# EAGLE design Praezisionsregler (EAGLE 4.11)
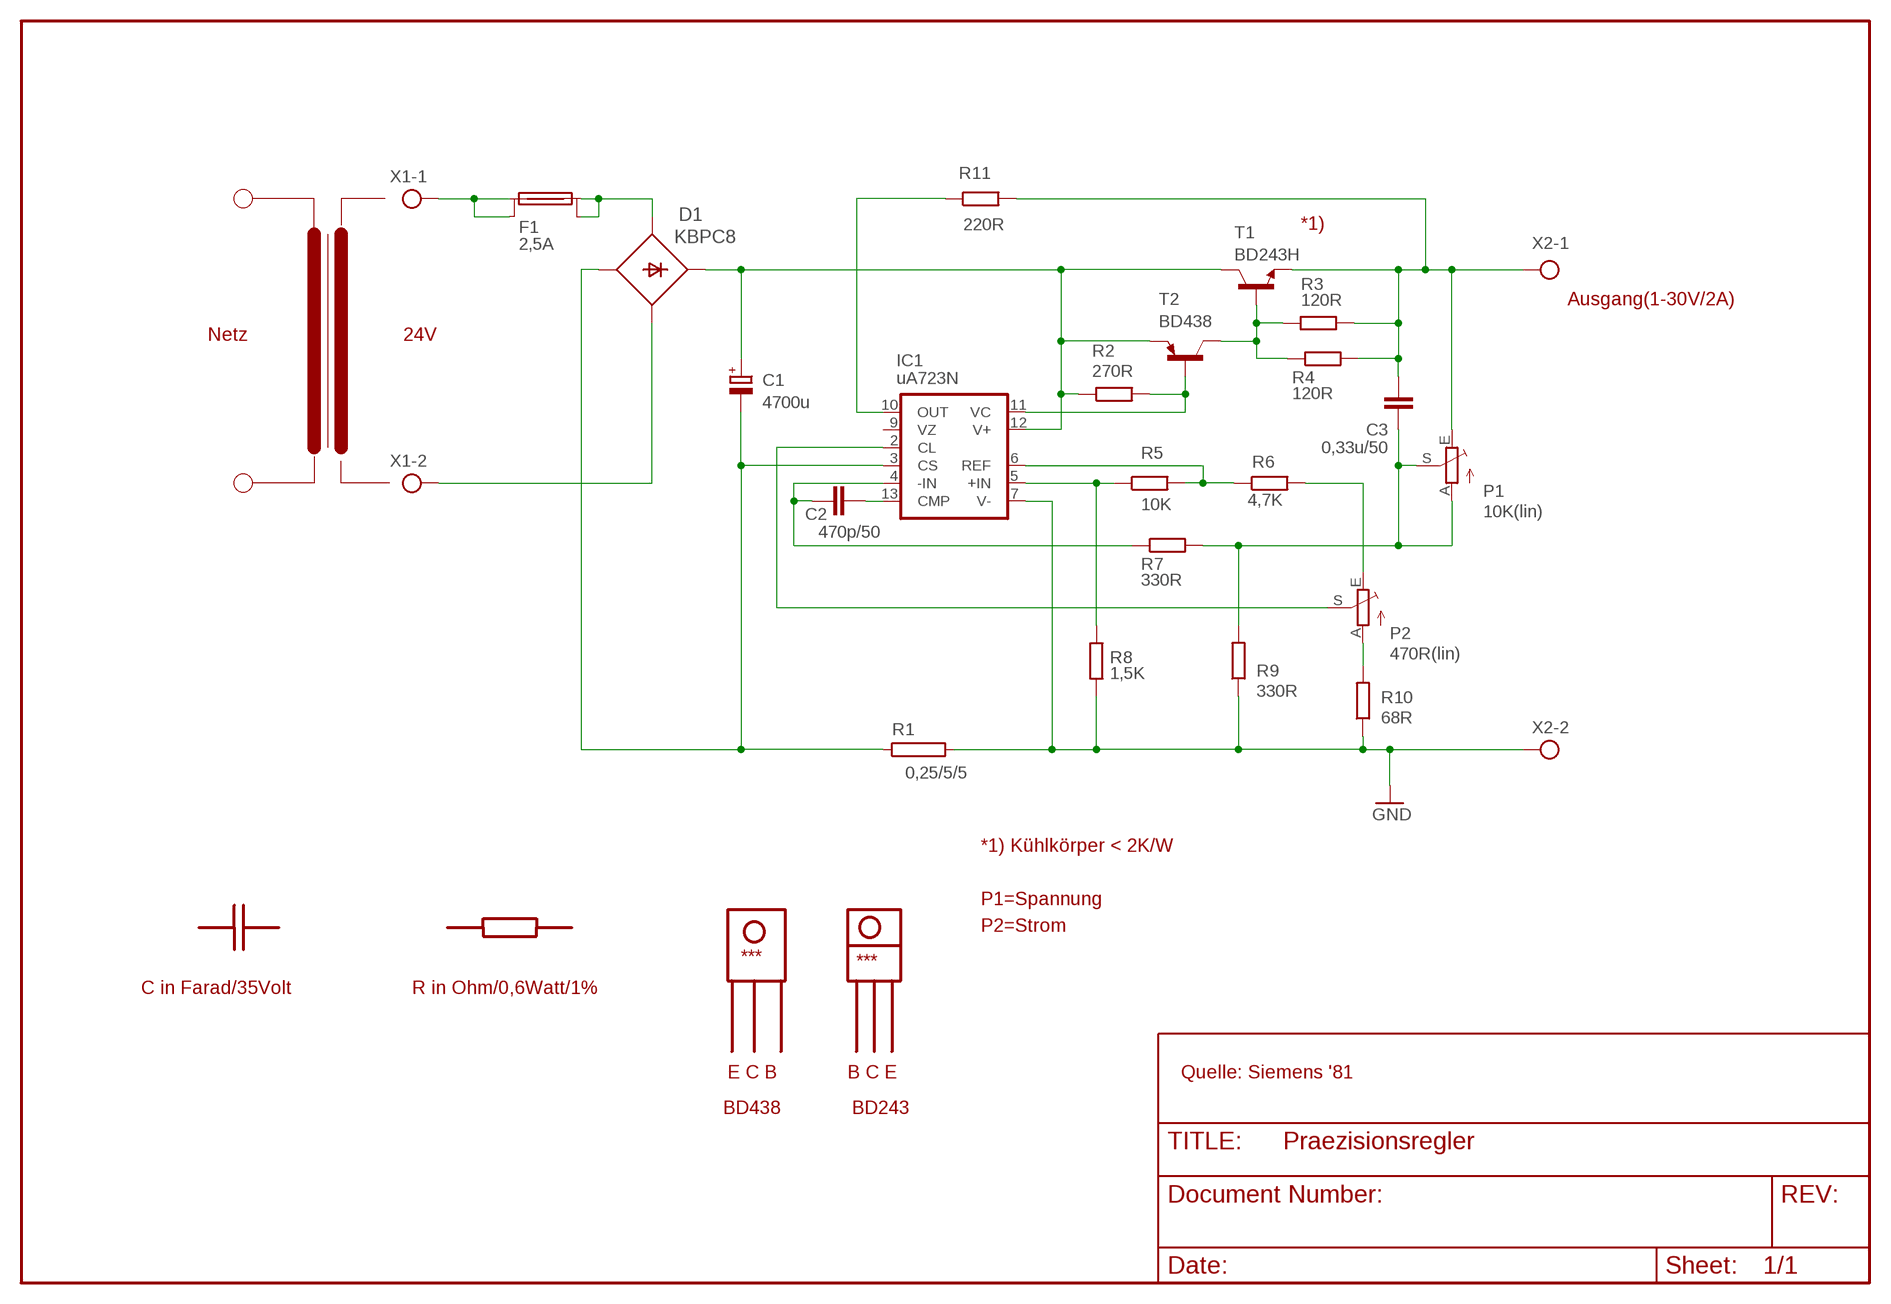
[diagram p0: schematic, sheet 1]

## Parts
C1  4700u  CPOL-EUE10-22.5  [EB22,5D]
C2  470p/50  C5/2.5  [C5B2.5]
C3  0,33u/50  C5/2.5  [C5B2.5]
D1  KBPC8  [KBPC8]
F1  2,5A  SHK20L  [SHK20L]
IC1  uA723N  [DIL14]
P1  10K(lin)  TRIM_EU-LI15  [LI15]
P2  470R(lin)  TRIM_EU-LI15  [LI15]
R1  0,25/5/5  RKH206-8  [KH206-8]
R2  270R  R-EU_0309/12  [0309/12]
R3  120R  R-EU_0309/12  [0309/12]
R4  120R  R-EU_0309/12  [0309/12]
R5  10K  R-EU_0207/10  [0207/10]
R6  4,7K  R-EU_0207/10  [0207/10]
R7  330R  R-EU_0207/10  [0207/10]
R8  1,5K  R-EU_0207/10  [0207/10]
R9  330R  R-EU_0207/10  [0207/10]
R10  68R  R-EU_0207/10  [0207/10]
R11  220R  R-EU_0207/10  [0207/10]
T1  BD243H  [TO220H]
T2  BD438  BD438V  [TO126]
X1  AK300/2  [AK300/2]
X2  AK300/2  [AK300/2]

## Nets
GND: IC1.7(V-) R1.2 R8.2 R9.1 R10.1 X2.2
N$1: F1.1A F1.1B X1.1
N$2: D1.AC2 F1.2A F1.2B
N$3: D1.AC1 X1.2
N$4: C1.+ D1.DC+ IC1.12(V+) R2.1 T1.2(C) T2.1(E)
N$5: C1.- D1.DC- IC1.3(CS) R1.1
N$6: IC1.5(+IN) R5.1 R8.1
N$7: IC1.10(OUT) R11.1
N$8: IC1.6(REF) R5.2 R6.1
N$9: IC1.2(CL) P2.S
N$10: P2.E R6.2
N$11: P2.A R10.2
N$12: C3.2 P1.A P1.S R7.2 R9.2
N$13: C2.1 IC1.4(-IN) R7.1
N$14: C3.1 P1.E R3.2 R4.2 R11.2 T1.3(E) X2.1
N$15: C2.2 IC1.13(CMP)
N$16: IC1.11(VC) R2.2 T2.3(B)
N$17: R3.1 R4.1 T1.1(B) T2.2(C)
Unconnected: IC1.9(VZ)

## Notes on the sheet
- *1)
- Ausgang(1-30V/2A)
- Netz | 24V
- *1) Kühlkörper < 2K/W
- P1=Spannung
- P2=Strom
- *** | ***
- C in Farad/35Volt | R in Ohm/0,6Watt/1%
- E C B | B C E | Quelle: Siemens '81
- BD438 | BD243

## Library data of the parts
C1 = rcl:CPOL-EU: POLARIZED CAPACITOR, European symbol
C2 C3 = capacitor-wima:C: CAPACITOR
D1 = IntergatedCircuits-mix:KBPC8: DIOTEC RECTIFIER
F1 = PassivParts:SHK20L: FUSE HOLDER 5 x 20 mm, SH contact, SHH1 Schukat, E1073 Buerklin
IC1 = linear:*723: Positive VOLTAGE REGULATOR
P1 P2 = pot:TRIM_EU-: POTENTIOMETER
R1 = resistor-power:R: Power Resitor
R2-R11 = rcl:R-EU_: RESISTOR, European symbol
T1 = transistor-mix:BD243: NPN TRANSISTOR
T2 = transistor-mix:BD438
X1 X2 = con-ptr500:AK300/2: CONNECTOR

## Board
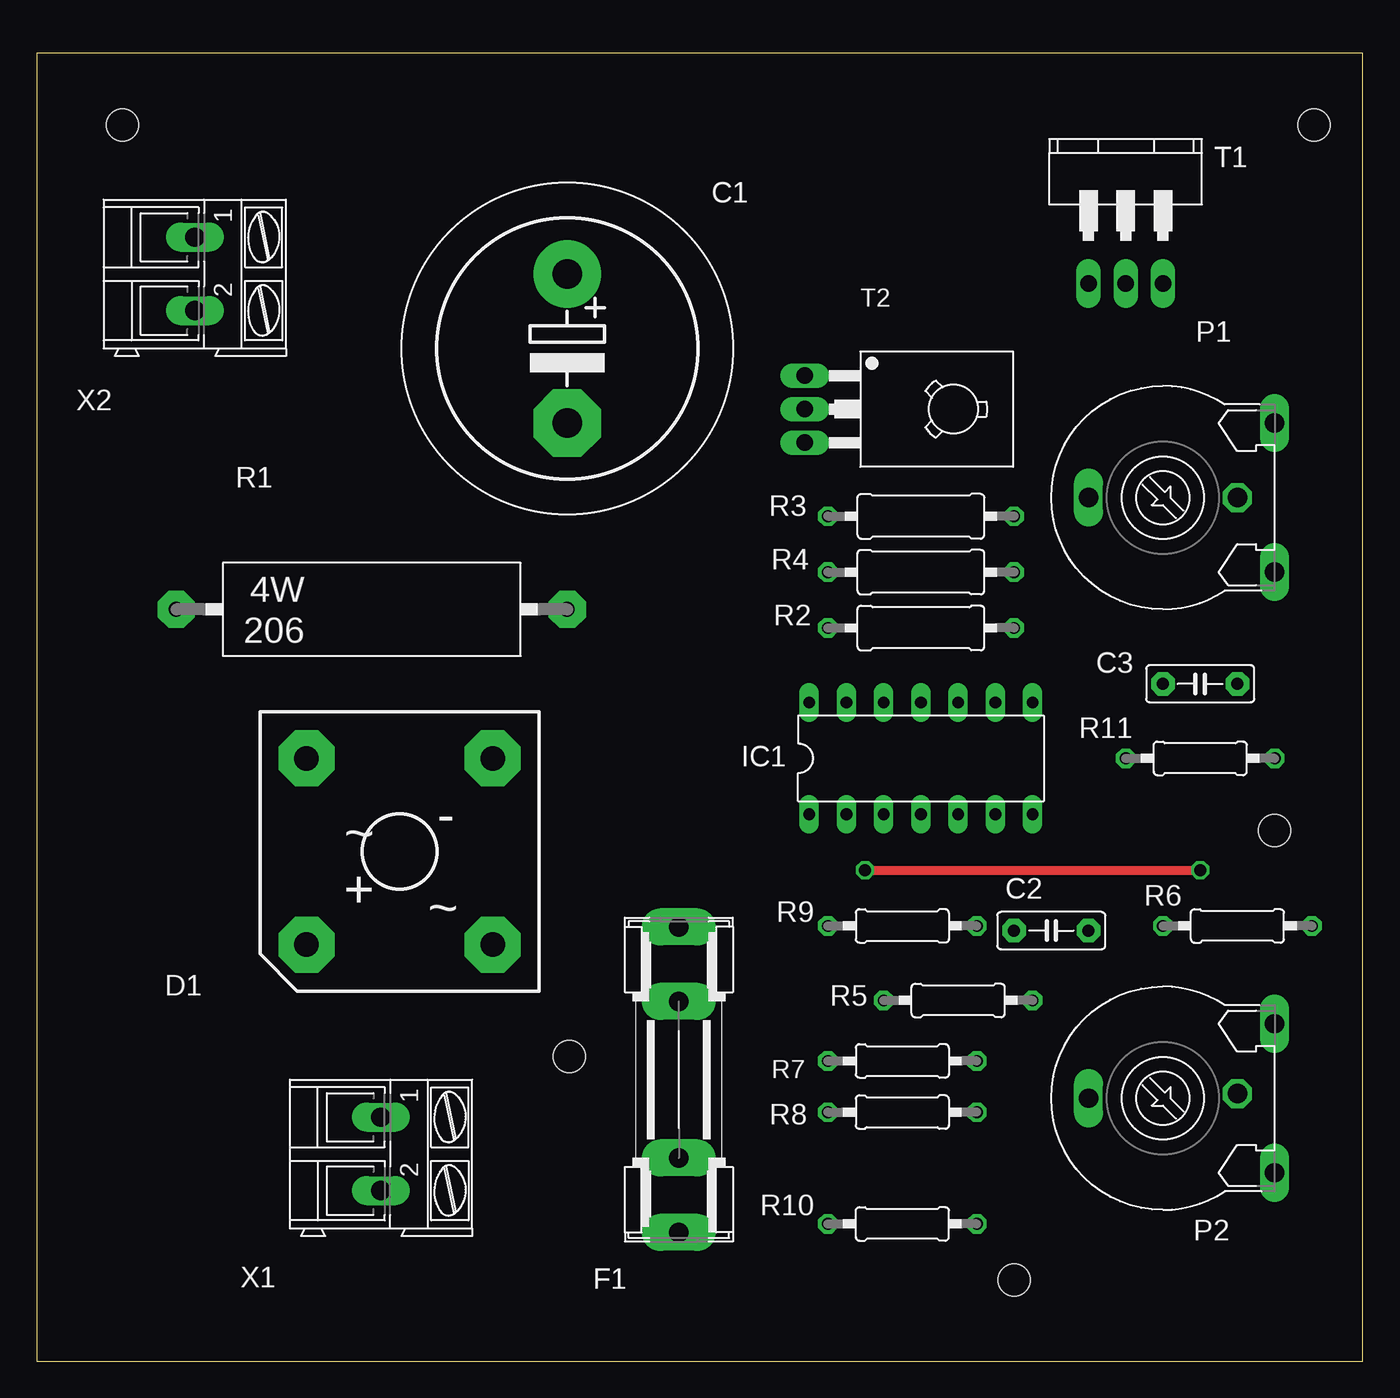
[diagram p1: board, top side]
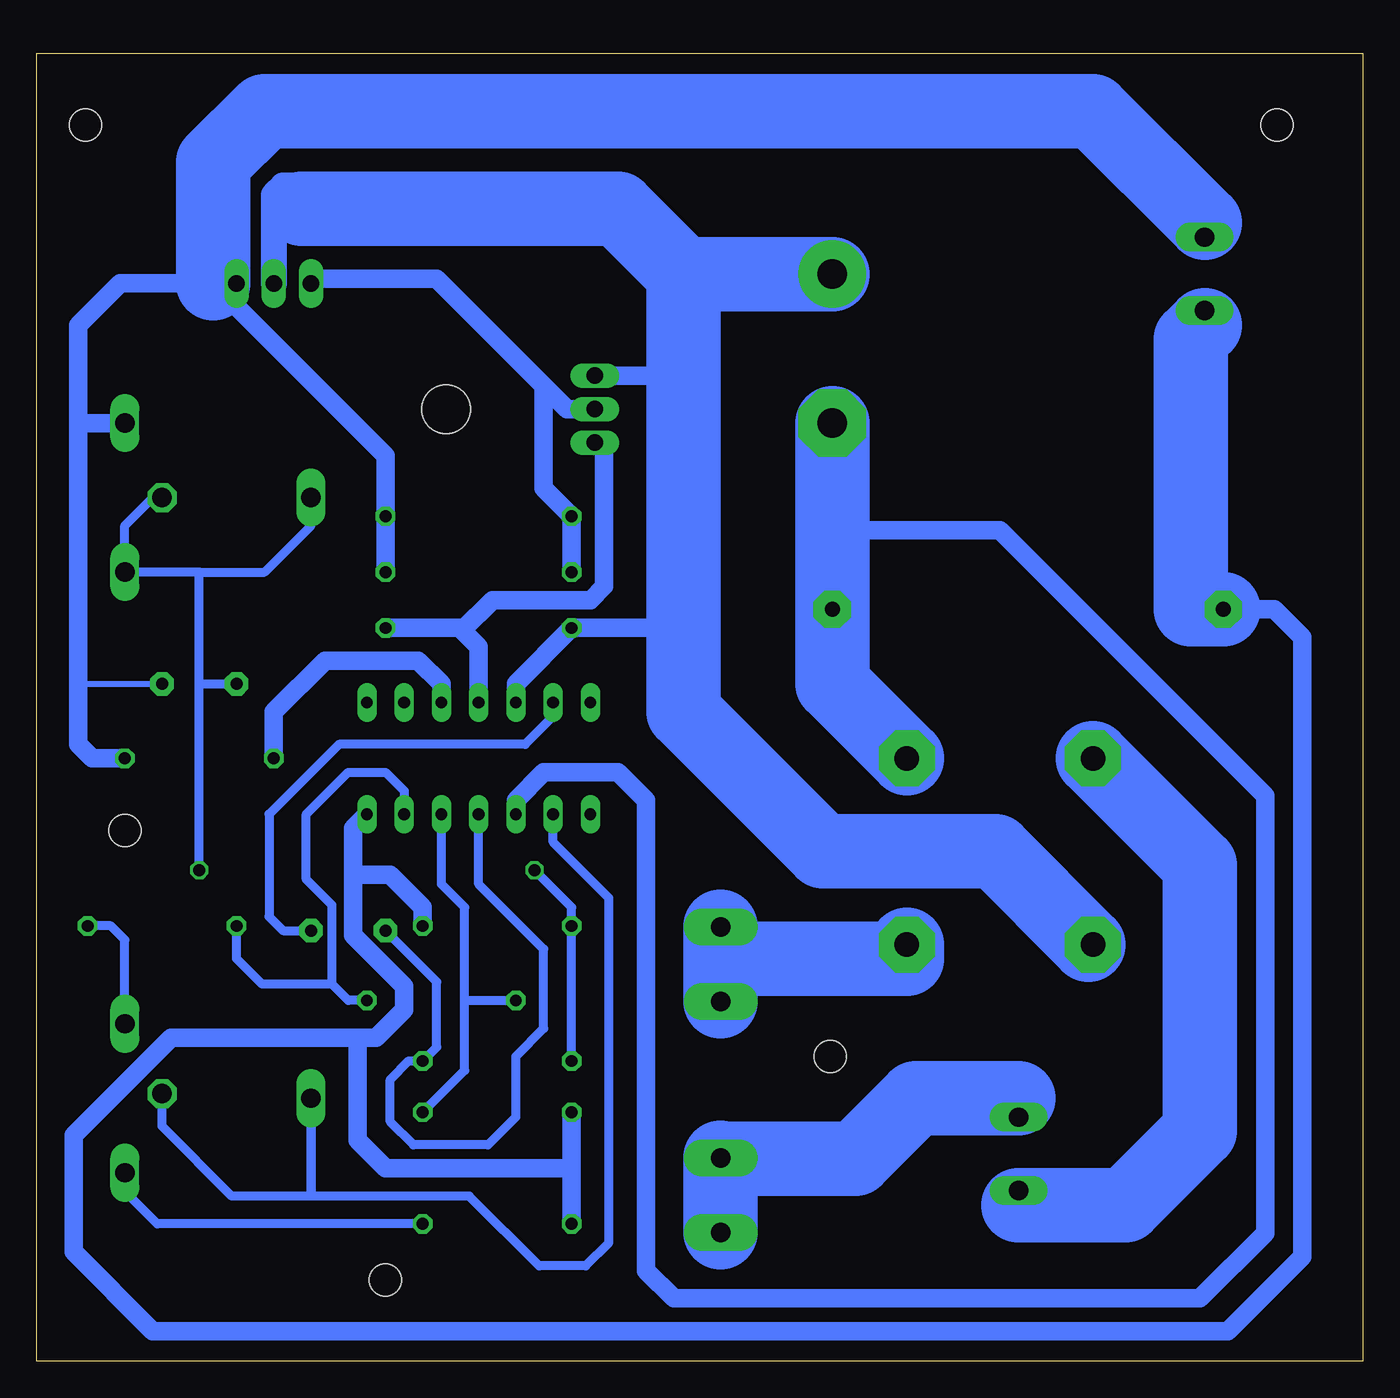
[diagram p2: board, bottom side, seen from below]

Size 90.47 x 89.2 mm. Coordinates in mm from the lower left corner, seen from the top.
Outline: 0,0 90.47,0 90.47,89.2 0,89.2 0,0
Copper layers (1*16): Top 0.035mm / dielectric 1.5mm / Bottom 0.035mm
Design rules "default": minimum track width 10mil, minimum drill 24mil, track to track 8mil, track to pad 8mil, pad to pad 8mil, via to via 8mil, smd to smd 8mil, copper to edge 40mil, drill to drill 8mil, minimum pad ring 10mil, minimum via ring 8mil, stop-mask expansion 4mil, vias tented up to drill 0mil, thermal gap 10mil
Holes 2.18 mm at 5.87,84.29 36.35,20.79 84.45,36.19 87.15,84.29 66.67,5.55

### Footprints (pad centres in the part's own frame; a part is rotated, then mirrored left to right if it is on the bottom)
EB22,5D = drill 2.007 pad 4.597 round: + -5.08,0 | drill 2.007 pad 4.597 octagon: - 5.08,0
C5B2.5 = drill 0.813 pad 1.6 octagon: 1 -2.54,0; 2 2.54,0
KBPC8 = drill 1.676 pad 3.81 octagon: AC1 -6.35,6.35; AC2 6.35,-6.35; DC+ -6.35,-6.35; DC- 6.35,6.35
SHK20L = drill 1.321 pad 2.54 long: 1A -10.414,0; 1B -5.334,0; 2A 10.414,0; 2B 5.334,0
DIL14 = drill 0.813 long: 1 -7.62,-3.81; 2 -5.08,-3.81; 3 -2.54,-3.81; 4 0,-3.81; 5 2.54,-3.81; 6 5.08,-3.81; 7 7.62,-3.81; 8 7.62,3.81; 9 5.08,3.81; 10 2.54,3.81; 11 0,3.81; 12 -2.54,3.81; 13 -5.08,3.81; 14 -7.62,3.81
LI15 = drill 1.321 long: A -5.08,-7.62; E 5.08,-7.62; S 0,5.08
KH206-8 = drill 1.016 pad 2.54 octagon: 1 -13.335,0; 2 13.335,0
0309/12 = drill 0.813 octagon: 1 -6.35,0; 2 6.35,0
0207/10 = drill 0.813 octagon: 1 -5.08,0; 2 5.08,0
TO220H = drill 1.118 long: 1 -2.54,-6.35; 2 0,-6.35; 3 2.54,-6.35
TO126 = drill 1.118 long: 1 -2.286,-5.08; 2 0,-5.08; 3 2.286,-5.08 | hole 3.302: 0,5.08
AK300/2 = drill 1.321 long: 1 -2.515,0; 2 2.489,0

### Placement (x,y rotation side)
C1  36.19,69.05 270 top
C2  69.21,29.36 0 top
C3  79.37,46.19 180 top
D1  24.76,34.76 0 top
F1  43.81,19.2 90 top
IC1  60.32,41.11 0 top
P1  76.83,58.89 90 top
P2  76.83,17.93 90 top
R1  22.86,51.27 180 top
R2  60.32,50 0 top
R3  60.32,57.62 0 top
R4  60.32,53.81 0 top
R5  62.86,24.6 0 top
R6  81.91,29.68 0 top
R7  59.05,20.47 180 top
R8  59.05,16.98 180 top
R9  59.05,29.68 180 top
R10  59.05,9.36 0 top
R11  79.37,41.11 0 top
T1  74.29,79.84 0 top
T2  57.46,64.92 270 top
X1  23.49,14.12 270 top
X2  10.79,74.13 270 top

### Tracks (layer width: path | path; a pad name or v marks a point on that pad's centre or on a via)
GND
  Bottom 1.27: 67.3,22.06 65.4,23.96 65.4,25.55 68.89,29.04 68.89,33.17 | 67.3,22.06 68.57,22.06 68.57,15.08 66.67,13.17 53.97,13.17 | R1.2 6.03,51.27 4.12,49.37 4.12,7.14 9.2,2.06 82.55,2.06 87.94,7.46 87.94,14.76 87.94,15.39 81.27,22.06 67.3,22.06 | 68.89,33.17 68.89,36.35 IC1.7 | R9.1 64.13,30.95 66.35,33.17 68.89,33.17 | R10.1 53.97,13.17 | 53.97,13.17 R8.2
  Bottom 2.54: 10.79,70.64 X2.2
  Bottom 5.08: R1.2 11.74,51.27 11.74,69.69 10.79,70.64
N$1
  Bottom 0.406: X1.1 23.49,17.93
  Bottom 5.08: 23.49,17.93 30.47,17.93 34.6,13.81 43.81,13.81 | 43.81,13.81 F1.1B | 43.81,13.81 F1.1A
N$2
  Bottom 5.08: D1.AC2 31.11,27.46 43.81,27.46 | 43.81,27.46 F1.2A | 43.81,27.46 F1.2B
N$3
  Bottom 0.406: 23.49,10.63 X1.2
  Bottom 5.08: 23.49,10.63 16.19,10.63 11.11,15.71 11.11,33.81 D1.AC1
N$4
  Bottom 0.406: D1.DC+ 18.73,28.41
  Bottom 1.27: IC1.12 57.78,46.19 R2.1 46.35,50 | 46.35,67.14 46.67,67.14 46.73,67.21 T2.1
  Bottom 1.778: 72.38,78.58 72.38,80.16 73.66,80.16 74.29,79.53 T1.2
  Bottom 5.08: 46.35,74.13 50.8,78.58 72.38,78.58 | 46.35,74.13 C1.+ | 18.73,28.41 25.08,34.76 36.83,34.76 46.35,44.28 46.35,50 46.35,67.14 46.35,74.13
N$5
  Bottom 1.27: IC1.3 57.78,38.25 55.88,40.16 50.8,40.16 48.89,38.25 48.89,6.18 46.98,4.28 11.11,4.28 6.66,8.73 6.66,38.57 24.76,56.67 36.19,56.67
  Bottom 5.08: D1.DC- 36.19,46.19 R1.1 36.19,56.67 C1.-
N$6
  Bottom 0.61: R8.1 61.27,19.84 61.27,24.6 | IC1.5 62.86,32.54 61.27,30.95 61.27,24.6 | 61.27,24.6 R5.1
N$7
  Bottom 1.27: IC1.10 62.86,46.19 64.45,47.78 70.8,47.78 74.29,44.28 R11.1
N$8
  Bottom 0.61: IC1.6 65.4,38.89 66.67,40.16 69.21,40.16 72.07,37.3 72.07,32.85 70.32,31.11 70.32,25.71 | 70.32,25.71 75.08,25.71 76.83,27.46 R6.1 | R5.2 69.21,24.6 70.32,25.71
N$9  (via drill 1.32)
  Bottom 0.61: IC1.2 55.24,35.39 51.43,31.58 51.43,8.09 53.02,6.5 56.19,6.5 60.96,11.27 71.75,11.27 | 71.75,11.27 P2.S 71.75,11.27 | 71.75,11.27 72.7,11.27 77.15,11.27 81.91,16.03 v81.91,18.25
N$10
  Bottom 0.61: R6.2 85.4,29.68 84.45,28.73 P2.E
N$11
  Bottom 0.61: P2.A 84.45,11.58 82.23,9.36 R10.2
N$12  (via drill 0.81, 1.32)
  Top 0.61: v56.51,33.49 v79.37,33.49
  Bottom 0.61: R7.2 R9.2 53.97,30.95 v56.51,33.49 | 79.37,53.81 P1.A 84.45,56.98 82.55,58.89 v81.91,58.89 | P1.S 71.75,56.98 74.92,53.81 79.37,53.81 | 79.37,46.19 79.37,53.81 | 79.37,46.19 C3.2 | v79.37,33.49 79.37,46.19
N$13
  Bottom 0.61: C2.1 63.18,25.87 63.18,21.42 R7.1 65.08,20.47 66.35,19.2 66.35,16.34 64.77,14.76 59.69,14.76 57.78,16.66 57.78,20.79 55.88,22.7 55.88,28.09 60.32,32.54 IC1.4
N$14
  Bottom 0.406: X2.1 10.79,77.62 10.79,78.58 | 78.42,73.5 T1.3 | 87.62,46.19 C3.1
  Bottom 1.27: R4.2 R3.2 66.67,61.75 76.83,71.91 T1.3 | 87.62,63.97 P1.E | 78.42,73.5 84.77,73.5 87.62,70.64 87.62,63.97 | 87.62,63.97 87.62,46.19 87.62,42.06 86.67,41.11 R11.2
  Bottom 5.08: 10.79,77.62 18.41,85.24 74.92,85.24 78.42,81.75 78.42,73.5
N$15
  Bottom 0.61: IC1.13 55.24,43.97 57.15,42.06 69.84,42.06 74.61,37.3 74.61,30.31 73.66,29.36 C2.2
N$16
  Bottom 1.27: R2.2 61.59,50 61.43,49.84 | 61.43,49.84 60.32,48.73 IC1.11 | T2.3 51.81,62.64 51.75,62.7 51.75,52.86 52.7,51.91 59.37,51.91 61.43,49.84 | 61.43,49.84
N$17
  Bottom 1.27: T2.2 54.29,64.92 55.72,66.35 | 55.72,66.35 63.18,73.81 71.75,73.81 T1.1 | R4.1 R3.1 55.88,59.52 55.88,66.19 55.72,66.35 | 55.72,66.35

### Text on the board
Document: Leiterpl. einseitig o. Siebd. o. Stoppl, Kupferaufl. 160um partiell verz., Mat. FR4-1,6mm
